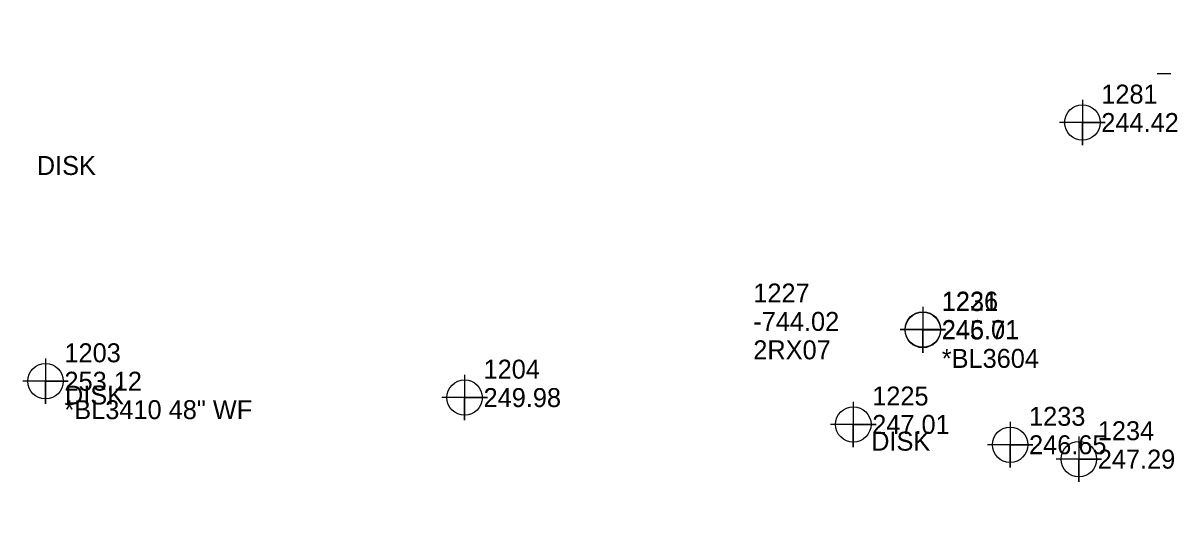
# Model space of a CAD drawing. Extents: x 2130621 to 2131998, y 642516 to 644503.
# Drawn here: x 2130991.9 to 2131142.4, y 643224.5 to 643288.8 of the extents above; entities that cross this region are included whole.
import ezdxf

# ---------------------------------------------------------------- set-up
doc = ezdxf.new("R2010")
doc.units = 0
for name, color, linetype in [('Exist Other Culture Fence Line Cogo Comment', 7, 'Continuous'), ('Exist Other Culture Fence Line Cogo Elevation', 7, 'Continuous'), ('Exist Other Culture Fence Line Cogo Number', 7, 'Continuous'), ('Exist Other Culture Fence Line Cogo Point CELL', 7, 'Continuous'), ('Exist Right of Way Monument Cogo Comment', 7, 'Continuous'), ('Exist Roads EOP', 7, 'Continuous'), ('Exist Utilities Power Joint Use Telephone Cogo Comment', 7, 'Continuous'), ('Exist Utilities Power Joint Use Telephone Cogo Elevation', 7, 'Continuous'), ('Exist Utilities Power Joint Use Telephone Cogo Number', 7, 'Continuous'), ('Exist Vegetation Woods Line Cogo Comment', 7, 'Continuous'), ('Exist Vegetation Woods Line Cogo Elevation', 7, 'Continuous'), ('Exist Vegetation Woods Line Cogo Number', 7, 'Continuous'), ('Exist Vegetation Woods Line Cogo Point CELL', 7, 'Continuous')]:
    doc.layers.add(name, color=color, linetype=linetype)

msp = doc.modelspace()

# ---------------------------------------------------------------- linework, layer by layer
at = {"layer": 'Exist Other Culture Fence Line Cogo Point CELL'}
for points in [[(2131131.81, 643278.61), (2131131.81, 643272.61), (2131131.81, 643275.61), (2131134.81, 643275.61), (2131128.81, 643275.61)], [(2131110.75, 643251.3), (2131110.75, 643245.3), (2131110.75, 643248.3), (2131113.75, 643248.3), (2131107.75, 643248.3)], [(2130994.93, 643244.48), (2130994.93, 643238.48), (2130994.93, 643241.48), (2130997.93, 643241.48), (2130991.93, 643241.48)], [(2131050.26, 643242.32), (2131050.26, 643236.32), (2131050.26, 643239.32), (2131053.26, 643239.32), (2131047.26, 643239.32)], [(2131101.57, 643238.78), (2131101.57, 643232.78), (2131101.57, 643235.78), (2131104.57, 643235.78), (2131098.57, 643235.78)]]:
    msp.add_lwpolyline(points, dxfattribs=at)
for centre in [(2131131.81, 643275.61), (2131110.75, 643248.3), (2130994.93, 643241.48), (2131050.26, 643239.32), (2131101.57, 643235.78)]:
    msp.add_circle(centre, 2.34, dxfattribs=at)
at = {"layer": 'Exist Roads EOP'}
msp.add_spline([(2131166.25, 643216.7), (2131171.81, 643218.72), (2131182.37, 643223.97), (2131191.81, 643231.15), (2131200.5, 643239.7), (2131208.81, 643249.07), (2131216.07, 643259), (2131218.72, 643264.35), (2131220.54, 643270.1), (2131222.84, 643282.01), (2131224.36, 643293.92), (2131224.88, 643317.79), (2131222.06, 643367.67), (2131218.54, 643416.81), (2131214.32, 643466.35), (2131209.17, 643515.67), (2131202.79, 643565.15), (2131195.05, 643613.99), (2131186.4, 643662.48), (2131176.01, 643711.41), (2131164.62, 643759.89), (2131151.87, 643807.85), (2131137.86, 643855.41), (2131122.57, 643902.86), (2131105.96, 643949.49), (2131091.53, 643988.04)], degree=3, dxfattribs=at)
at = {"layer": 'Exist Vegetation Woods Line Cogo Point CELL'}
for points in [[(2131144.7, 643285.05), (2131144.7, 643279.05), (2131144.7, 643282.05), (2131147.7, 643282.05), (2131141.7, 643282.05)], [(2131110.75, 643251.24), (2131110.75, 643245.24), (2131110.75, 643248.24), (2131113.75, 643248.24), (2131107.75, 643248.24)], [(2131122.27, 643236.1), (2131122.27, 643230.1), (2131122.27, 643233.1), (2131125.27, 643233.1), (2131119.27, 643233.1)], [(2131131.35, 643234.2), (2131131.35, 643228.2), (2131131.35, 643231.2), (2131134.35, 643231.2), (2131128.35, 643231.2)]]:
    msp.add_lwpolyline(points, dxfattribs=at)
for centre in [(2131110.75, 643248.24), (2131122.27, 643233.1), (2131131.35, 643231.2)]:
    msp.add_circle(centre, 2.34, dxfattribs=at)

# ---------------------------------------------------------------- texts
at = {"layer": 'Exist Other Culture Fence Line Cogo Comment'}
msp.add_text('*BL3410 48" WF', height=2.5, dxfattribs=at).set_placement((2130997.43, 643236.48))
at = {"layer": 'Exist Other Culture Fence Line Cogo Elevation'}
for s, p in [('244.42', (2131134.31, 643274.36)), ('246.01', (2131113.25, 643247.05)), ('253.12', (2130997.43, 643240.23)), ('249.98', (2131052.76, 643238.07)), ('247.01', (2131104.07, 643234.53))]:
    msp.add_text(s, height=2.5, dxfattribs=at).set_placement(p)
at = {"layer": 'Exist Other Culture Fence Line Cogo Number'}
for s, p in [('1281', (2131134.31, 643278.11)), ('1226', (2131113.25, 643250.8)), ('1203', (2130997.43, 643243.98)), ('1204', (2131052.76, 643241.82)), ('1225', (2131104.07, 643238.28))]:
    msp.add_text(s, height=2.5, dxfattribs=at).set_placement(p)
at = {"layer": 'Exist Right of Way Monument Cogo Comment'}
for p in [(2130993.78, 643268.69), (2130997.5, 643238.41), (2131103.93, 643232.32)]:
    msp.add_text('DISK', height=2.5, dxfattribs=at).set_placement(p)
at = {"layer": 'Exist Utilities Power Joint Use Telephone Cogo Comment'}
msp.add_text('2RX07', height=2.5, dxfattribs=at).set_placement((2131088.37, 643244.37))
at = {"layer": 'Exist Utilities Power Joint Use Telephone Cogo Elevation'}
msp.add_text('-744.02', height=2.5, dxfattribs=at).set_placement((2131088.37, 643248.12))
at = {"layer": 'Exist Utilities Power Joint Use Telephone Cogo Number'}
msp.add_text('1227', height=2.5, dxfattribs=at).set_placement((2131088.37, 643251.87))
at = {"layer": 'Exist Vegetation Woods Line Cogo Comment'}
msp.add_text('*BL3604', height=2.5, dxfattribs=at).set_placement((2131113.25, 643243.24))
at = {"layer": 'Exist Vegetation Woods Line Cogo Elevation'}
for s, p in [('245.71', (2131113.25, 643246.99)), ('246.65', (2131124.77, 643231.85)), ('247.29', (2131133.85, 643229.95))]:
    msp.add_text(s, height=2.5, dxfattribs=at).set_placement(p)
at = {"layer": 'Exist Vegetation Woods Line Cogo Number'}
for s, p in [('1231', (2131113.25, 643250.74)), ('1233', (2131124.77, 643235.6)), ('1234', (2131133.85, 643233.7))]:
    msp.add_text(s, height=2.5, dxfattribs=at).set_placement(p)

doc.saveas('drawing.dxf')
